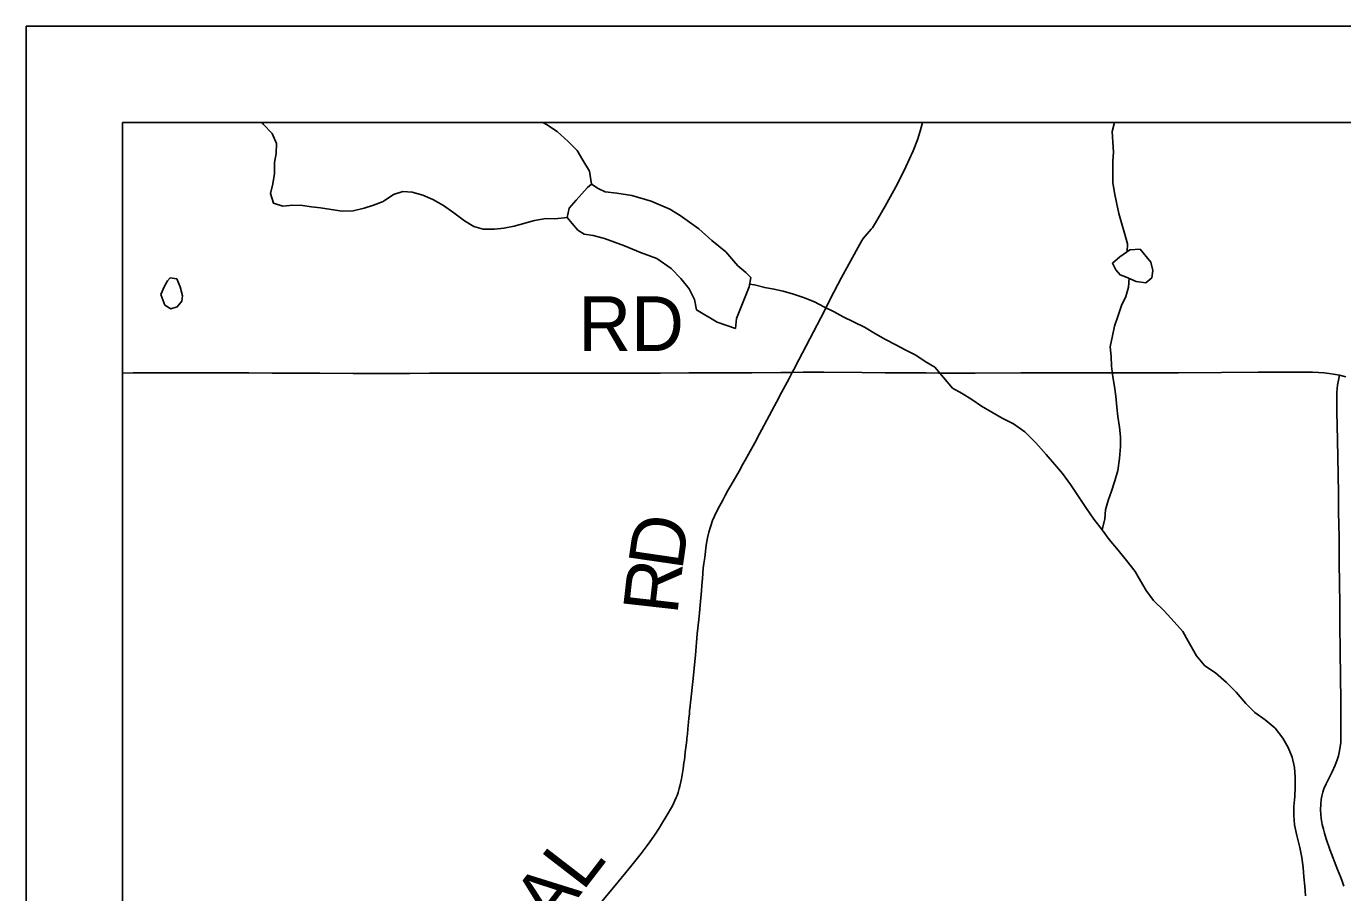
# Model space of a CAD drawing. Extents: x 0 to 34, y 0 to 22.
# Drawn here: x 13.344 to 14.711, y 19.125 to 20.024 of the extents above; entities that cross this region are included whole.
import ezdxf

# ---------------------------------------------------------------- set-up
doc = ezdxf.new("R2010")
doc.units = 0
for name, color, linetype in [('GM_X_Corporation', 7, 'Continuous'), ('GM_X_County_Road', 7, 'Continuous'), ('GM_X_County_Road_Text', 7, 'Continuous'), ('GM_X_Minor_Lake', 7, 'Continuous'), ('GM_X_Minor_River', 7, 'Continuous'), ('GM_X_Township_Road', 7, 'Continuous'), ('GM_X_Township_Road_Text', 7, 'Continuous'), ('SH_Data', 7, 'Continuous')]:
    doc.layers.add(name, color=color, linetype=linetype)

msp = doc.modelspace()

# ---------------------------------------------------------------- linework, layer by layer
at = {"layer": 'GM_X_Corporation'}
msp.add_lwpolyline([(18.775, 16.6777), (18.7553, 18.174), (18.7532, 18.52), (18.7531, 18.5321), (18.758, 19.3951), (18.7506, 19.9239), (13.4438, 19.9239), (13.4438, 15.6034)], dxfattribs=at)
at = {"layer": 'GM_X_County_Road'}
for points in [[(14.1393, 19.6647), (14.1409, 19.6677), (14.1462, 19.6778), (14.1616, 19.7069), (14.1727, 19.7285), (14.1788, 19.7407), (14.1906, 19.7633), (14.2112, 19.8009), (14.2129, 19.8036), (14.2214, 19.8135), (14.2228, 19.8147), (14.2259, 19.82), (14.2358, 19.8371), (14.2486, 19.8605), (14.2575, 19.8782), (14.265, 19.8946), (14.2695, 19.9061), (14.2723, 19.9149), (14.2743, 19.9227), (14.2746, 19.9239)], [(13.9394, 19.1131), (13.9555, 19.1321), (13.9728, 19.1533), (13.9824, 19.1655), (13.9888, 19.1738), (13.9914, 19.1774), (13.9981, 19.1869), (13.9998, 19.1895), (14.0011, 19.1916), (14.0037, 19.1958), (14.0084, 19.2038), (14.015, 19.215), (14.0189, 19.2234), (14.0198, 19.2257), (14.0207, 19.2287), (14.0219, 19.2328), (14.0226, 19.2352), (14.0245, 19.243), (14.026, 19.2534), (14.0265, 19.2564), (14.0269, 19.2595), (14.0273, 19.2625), (14.0278, 19.2662), (14.0283, 19.2704), (14.0288, 19.2753), (14.0294, 19.2802), (14.0297, 19.2832), (14.0299, 19.2851), (14.0304, 19.2894), (14.031, 19.2949), (14.0316, 19.3017), (14.0321, 19.306), (14.0325, 19.3103), (14.0328, 19.3134), (14.0332, 19.3182), (14.0337, 19.3225), (14.0339, 19.3249), (14.0361, 19.344), (14.0388, 19.3711), (14.0407, 19.3934), (14.0422, 19.4082), (14.0429, 19.415), (14.0436, 19.423), (14.045, 19.4379), (14.0455, 19.4434), (14.0461, 19.4509), (14.047, 19.4614), (14.0476, 19.4663), (14.0484, 19.4725), (14.0501, 19.4855), (14.0515, 19.4929), (14.0528, 19.4989), (14.0543, 19.5044), (14.0566, 19.5109), (14.0586, 19.5155), (14.0622, 19.5228), (14.0671, 19.5321), (14.0698, 19.5371), (14.0723, 19.542), (14.0756, 19.5472), (14.0843, 19.5623), (14.0882, 19.5693), (14.0906, 19.5737), (14.0938, 19.5797), (14.1004, 19.5917), (14.1054, 19.601), (14.1154, 19.6196), (14.121, 19.63), (14.1231, 19.6338), (14.1283, 19.6437), (14.136, 19.6583), (14.1393, 19.6647)]]:
    msp.add_lwpolyline(points, dxfattribs=at)
at = {"layer": 'GM_X_Minor_Lake'}
for p, q in [((14.4856, 19.764), (14.4966, 19.7592)), ((13.4835, 19.7457), (13.4877, 19.7344)), ((14.0814, 19.7207), (14.0945, 19.7534))]:
    msp.add_line(p, q, dxfattribs=at)
for points in [[(14.0945, 19.7534), (14.0963, 19.7632), (14.091, 19.7685), (14.083, 19.7753), (14.0704, 19.7897), (14.056, 19.8017), (14.0423, 19.8138), (14.0229, 19.8274), (14.0122, 19.8341), (13.9928, 19.8424), (13.9727, 19.8484), (13.9572, 19.8506), (13.945, 19.852), (13.9378, 19.8554), (13.931, 19.8599), (13.9268, 19.8565), (13.9208, 19.85), (13.9148, 19.8435), (13.9076, 19.8351), (13.9054, 19.8256), (13.9107, 19.8192), (13.9168, 19.8124), (13.9233, 19.8083), (13.9327, 19.8068), (13.9445, 19.8038), (13.9548, 19.7997), (13.965, 19.796), (13.9817, 19.7892), (13.9988, 19.7829), (14.0136, 19.7727), (14.0235, 19.7621), (14.0323, 19.7515), (14.0377, 19.7405), (14.04, 19.7296), (14.0613, 19.7168), (14.0803, 19.7104), (14.0814, 19.7207)], [(14.4966, 19.7592), (14.5065, 19.7577), (14.5129, 19.763), (14.514, 19.7706), (14.5117, 19.779), (14.5006, 19.7926), (14.49, 19.7918), (14.4795, 19.7845), (14.4719, 19.778), (14.4753, 19.7712), (14.4799, 19.7659), (14.4856, 19.764)], [(13.4877, 19.7344), (13.4938, 19.7306), (13.5006, 19.7329), (13.5055, 19.7386), (13.5062, 19.7443), (13.5035, 19.7534), (13.5001, 19.7617), (13.4932, 19.7628), (13.4906, 19.7598), (13.4872, 19.7541), (13.4835, 19.7457)]]:
    msp.add_lwpolyline(points, dxfattribs=at)
at = {"layer": 'GM_X_Minor_River'}
for points in [[(13.9054, 19.8256), (13.8929, 19.8241), (13.8834, 19.8244), (13.8716, 19.8224), (13.8504, 19.8163), (13.8398, 19.8143), (13.83, 19.8135), (13.8182, 19.8134), (13.8087, 19.816), (13.7989, 19.8221), (13.7878, 19.8304), (13.7772, 19.8379), (13.7662, 19.8443), (13.7555, 19.8488), (13.7445, 19.8518), (13.735, 19.8525), (13.7252, 19.8494), (13.7146, 19.8421), (13.7044, 19.8383), (13.6946, 19.8352), (13.6832, 19.8325), (13.6718, 19.8321), (13.6604, 19.8339), (13.6494, 19.8354), (13.64, 19.8364), (13.6305, 19.8379), (13.6206, 19.8382), (13.6104, 19.8374), (13.6005, 19.8404), (13.5974, 19.8503), (13.5997, 19.8605), (13.6015, 19.8712), (13.6015, 19.8825), (13.6033, 19.892), (13.6036, 19.9023), (13.599, 19.9125), (13.5899, 19.9223), (13.5884, 19.9239)], [(13.931, 19.8599), (13.9286, 19.8736), (13.9218, 19.8849), (13.916, 19.8951), (13.9065, 19.9042), (13.8951, 19.9148), (13.8841, 19.9219), (13.8803, 19.9239)], [(14.4871, 19.7897), (14.4877, 19.7982), (14.4843, 19.8092), (14.4812, 19.8198), (14.4785, 19.8297), (14.4762, 19.841), (14.4742, 19.8509), (14.4723, 19.8619), (14.4722, 19.8736), (14.4725, 19.8839), (14.4729, 19.8934), (14.4724, 19.9036), (14.4716, 19.9146), (14.474, 19.9239)], [(14.4611, 19.5013), (14.4641, 19.5127), (14.4648, 19.5222), (14.4674, 19.5317), (14.4711, 19.5416), (14.4745, 19.5522), (14.4775, 19.5629), (14.4793, 19.5754), (14.4804, 19.5879), (14.4803, 19.5978), (14.4791, 19.6077), (14.4776, 19.619), (14.4764, 19.6285), (14.4756, 19.6399), (14.474, 19.6501), (14.4725, 19.66), (14.4709, 19.671), (14.4705, 19.6812), (14.4697, 19.6911), (14.4719, 19.7025), (14.4741, 19.7128), (14.4778, 19.7238), (14.4812, 19.734), (14.4857, 19.7436), (14.4887, 19.7531), (14.4893, 19.7624)], [(14.6725, 19.1214), (14.6717, 19.1316), (14.6709, 19.1411), (14.6701, 19.151), (14.6685, 19.1612), (14.6666, 19.1715), (14.6635, 19.184), (14.6611, 19.195), (14.6603, 19.2048), (14.6603, 19.2143), (14.6614, 19.2246), (14.6617, 19.2344), (14.6617, 19.2447), (14.6612, 19.2545), (14.6585, 19.2652), (14.6543, 19.2754), (14.649, 19.2852), (14.641, 19.2954), (14.6307, 19.3041), (14.62, 19.3116), (14.6105, 19.3211), (14.6006, 19.3328), (14.5903, 19.343), (14.5789, 19.3528), (14.5679, 19.3603), (14.5591, 19.3705), (14.5507, 19.3857), (14.545, 19.3959), (14.5362, 19.4057), (14.5255, 19.4174), (14.5145, 19.428), (14.5069, 19.4382), (14.5011, 19.4484), (14.4954, 19.4582), (14.4866, 19.4696), (14.4778, 19.4802), (14.4687, 19.4911), (14.4611, 19.5013), (14.4527, 19.5123), (14.445, 19.5233), (14.4374, 19.535), (14.4283, 19.5482), (14.4199, 19.5596), (14.4119, 19.5694), (14.4031, 19.5796), (14.3924, 19.5917), (14.381, 19.603), (14.3692, 19.6113), (14.3574, 19.6173), (14.3468, 19.6233), (14.3361, 19.6297), (14.3259, 19.6365), (14.316, 19.6429), (14.3057, 19.6485), (14.2966, 19.6595), (14.2874, 19.6701), (14.2775, 19.6761), (14.2677, 19.6825), (14.2566, 19.6881), (14.2468, 19.6934), (14.2361, 19.699), (14.2259, 19.7047), (14.2145, 19.7115), (14.1924, 19.7223), (14.1829, 19.7276), (14.1723, 19.7329), (14.1624, 19.7381), (14.151, 19.7423), (14.1408, 19.746), (14.1301, 19.749), (14.1203, 19.7512), (14.1108, 19.7527), (14.1001, 19.7557), (14.095, 19.7562)]]:
    msp.add_lwpolyline(points, dxfattribs=at)
at = {"layer": 'GM_X_Township_Road'}
for points in [[(13.4438, 19.664), (13.4549, 19.6641), (13.4767, 19.6641), (13.5078, 19.6642), (13.535, 19.6642), (13.5543, 19.6642), (13.5749, 19.6641), (13.599, 19.664), (13.6189, 19.6639), (13.6486, 19.6638), (13.6832, 19.6636), (13.7077, 19.6637), (13.7421, 19.6637), (13.7625, 19.6638), (13.7705, 19.6638), (13.8021, 19.6638), (13.8221, 19.6638), (13.8606, 19.6638), (13.8821, 19.6638), (13.9009, 19.6638), (13.92, 19.6638), (13.9332, 19.6638), (13.9553, 19.6638), (13.9852, 19.664), (14.002, 19.664), (14.0319, 19.6641), (14.0454, 19.6642), (14.0631, 19.6643), (14.0973, 19.6644), (14.1274, 19.6645), (14.1393, 19.6647)], [(14.1393, 19.6647), (14.1507, 19.6649), (14.1722, 19.6649), (14.2117, 19.6646), (14.2359, 19.6644), (14.2553, 19.6643), (14.2785, 19.6641), (14.2913, 19.664)], [(14.2913, 19.664), (14.3012, 19.664), (14.3293, 19.664), (14.3768, 19.6641), (14.4107, 19.6641), (14.4299, 19.6641), (14.454, 19.6642), (14.4765, 19.6642), (14.5119, 19.6642), (14.5404, 19.6643), (14.5851, 19.6645), (14.6232, 19.6648), (14.6544, 19.665), (14.6657, 19.6649), (14.6725, 19.6649), (14.6796, 19.6648), (14.6858, 19.6645), (14.6914, 19.6642), (14.6971, 19.6634), (14.7014, 19.6628), (14.7077, 19.6618)], [(14.7122, 19.1314), (14.7104, 19.1368), (14.7091, 19.1405), (14.7057, 19.1488), (14.6978, 19.1694), (14.6938, 19.1807), (14.6921, 19.1866), (14.691, 19.1908), (14.6899, 19.1955), (14.6889, 19.2018), (14.6884, 19.2059), (14.6881, 19.2106), (14.6883, 19.2165), (14.6888, 19.2214), (14.6893, 19.2248), (14.6903, 19.2291), (14.6915, 19.2324), (14.6939, 19.2377), (14.6968, 19.2432), (14.7002, 19.2502), (14.7032, 19.257), (14.7053, 19.2626), (14.7066, 19.2667), (14.7078, 19.2718), (14.7086, 19.2763), (14.709, 19.2802), (14.7093, 19.2842), (14.7093, 19.2883), (14.7093, 19.2956), (14.7093, 19.3022), (14.709, 19.3288), (14.7088, 19.3443), (14.7083, 19.3797), (14.7082, 19.3987), (14.708, 19.4206), (14.7078, 19.4495), (14.7076, 19.4636), (14.7073, 19.4934), (14.7069, 19.52), (14.7066, 19.5387), (14.7063, 19.5583), (14.7057, 19.5946), (14.7051, 19.6234), (14.7049, 19.6321), (14.705, 19.6376), (14.7051, 19.6438), (14.7054, 19.6479), (14.7058, 19.6513), (14.7067, 19.6565), (14.7077, 19.6618)], [(14.7077, 19.6618), (14.7145, 19.6601)]]:
    msp.add_lwpolyline(points, dxfattribs=at)
at = {"layer": 'SH_Data'}
for p, q in [((13.3438, 20.0239), (20.3438, 20.0239)), ((13.3438, 20.0239), (13.3438, 13.0239)), ((13.4438, 19.9239), (13.4438, 13.1239)), ((13.4438, 19.9239), (20.2438, 19.9239))]:
    msp.add_line(p, q, dxfattribs=at)

# ---------------------------------------------------------------- texts
at = {"layer": 'GM_X_County_Road_Text'}
for s, rotation, p in [('D', 81.6911, (14.025, 19.4582)), ('R', 83.5818, (14.0199, 19.4123)), ('L', 52.387, (13.9216, 19.1253)), ('A', 52.3872, (13.8911, 19.0857))]:
    msp.add_text(s, height=0.0568, rotation=rotation, dxfattribs=at).set_placement(p)
at = {"layer": 'GM_X_Township_Road_Text'}
msp.add_text('RD', height=0.05682, rotation=0, dxfattribs=at).set_placement((13.9171, 19.6869))

doc.saveas('drawing.dxf')
